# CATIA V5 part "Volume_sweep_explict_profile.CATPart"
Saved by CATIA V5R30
Part number: Part1
Bounding box of the stored display mesh (mm): x -27.367 to 27.367, y -27.346 to 38.443, z 0 to 133.822
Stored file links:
  D:\PROJECTS\CATIA V56R 2020\Resources\Parts File\c17_catia_v6_6r2020_prt\Volume_sweep_explict_profile.CATPart
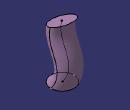
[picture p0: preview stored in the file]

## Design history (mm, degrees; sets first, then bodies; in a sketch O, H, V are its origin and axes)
Set1
  Sketch1 on xy-plane, origin (0, 0, 0), H (1, 0, 0), V (0, 1, 0)
    circle A1 centre (0, 0) radius 27.367
  Sketch2 on yz-plane, origin (0, 0, 0), H (0, 1, 0), V (0, 0, 1)
    spline S1 through (0, 0) (11.9407, 56.843) (-3.4307, 102.6672) (-1.4005, 123.8391)
    point P1 (0, 0)
    coincidence: P1 O
  Sweep1: type Unspec, Profile Sketch1, Guide Sketch2
Body1 (main body)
